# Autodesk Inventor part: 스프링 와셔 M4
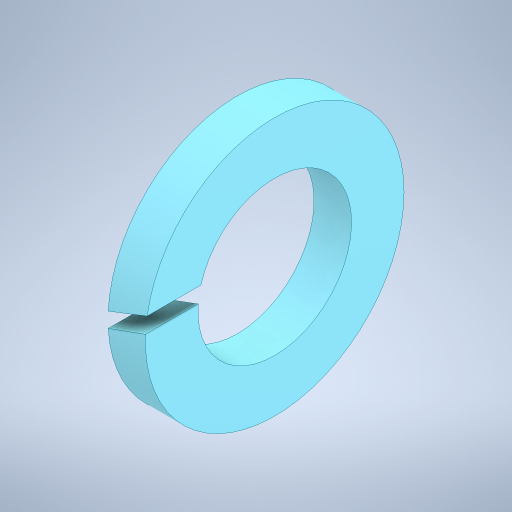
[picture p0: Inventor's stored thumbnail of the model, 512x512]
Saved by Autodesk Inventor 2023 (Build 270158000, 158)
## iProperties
Created: 2026-07
Part Number: 스프링 와셔 M4
Material: 강철, 연강
Description: 스프링 잠금 와셔
Document SubType Name: Modeling
Designer: home
Density: 7.85 g/cm^3
Appearance: 기본값
Author: jhkim
Sending System: Autodesk Inventor 2027
Preprocessor: ST-DEVELOPER v20.1
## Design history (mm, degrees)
feature "Solid1"
node "솔리드1"
